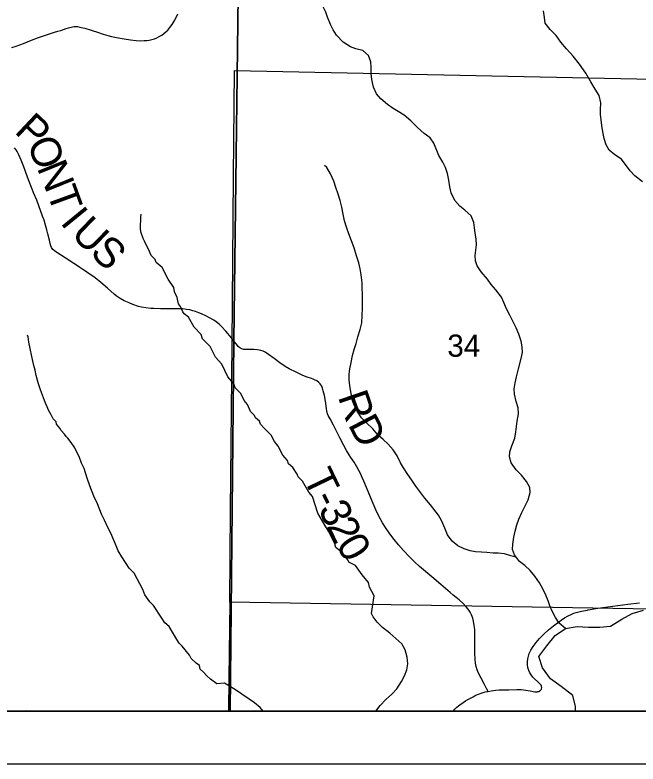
# Model space of a CAD drawing. Extents: x 0 to 34, y -8.9 to 22.
# Drawn here: x 27.768 to 28.944, y 14.5 to 15.913 of the extents above; entities that cross this region are included whole.
import ezdxf

# ---------------------------------------------------------------- set-up
doc = ezdxf.new("R2010")
doc.units = 0
for name, color, linetype in [('GM_X_Corporation', 7, 'Continuous'), ('GM_X_County_Road', 7, 'Continuous'), ('GM_X_Minor_River', 7, 'Continuous'), ('GM_X_Section_Text', 7, 'Continuous'), ('GM_X_Township_Road', 7, 'Continuous'), ('GM_X_Township_Road_Text', 7, 'Continuous'), ('SH_Data', 7, 'Continuous')]:
    doc.layers.add(name, color=color, linetype=linetype)

msp = doc.modelspace()

# ---------------------------------------------------------------- linework, layer by layer
at = {"layer": 'GM_X_Corporation'}
msp.add_lwpolyline([(23.7167, 19.34), (23.7167, 14.6), (30.5167, 14.6)], dxfattribs=at)
for points in [[(23.7167, 15.9913), (23.7167, 14.6), (28.1739, 14.6), (28.1809, 15.2987), (28.1918, 16.1509), (28.1846, 16.3341), (28.1817, 16.6637), (28.1928, 16.8054), (28.1882, 17.3108), (27.911, 17.3104), (27.4798, 17.3159), (27.0561, 17.3117), (26.7292, 17.3169), (26.394, 17.3229), (26.1361, 17.3278), (26.135, 17.3055), (26.1186, 15.9366), (25.7922, 15.939), (25.6785, 15.9418), (24.8268, 15.964), (24.2771, 15.9807), (24.0651, 15.9828)], [(28.1739, 14.6), (30.5167, 14.6), (30.5167, 16.7663), (30.4571, 16.7673), (29.5528, 16.7835), (28.3182, 16.8002), (28.1928, 16.8054), (28.1817, 16.6637), (28.1846, 16.3341), (28.1918, 16.1509), (28.1809, 15.2987)], [(29.0629, 15.7906), (29.0488, 14.7907), (28.1732, 14.8057), (28.1747, 14.9791), (28.1775, 15.2925), (28.1801, 15.6079), (28.182, 15.8086)], [(28.1707, 14.6), (29.0457, 14.6), (29.0488, 14.7907), (28.1732, 14.8057), (28.1713, 14.6617)]]:
    msp.add_lwpolyline(points, close=True, dxfattribs=at)
at = {"layer": 'GM_X_County_Road'}
for points in [[(28.6608, 14.6368), (28.6666, 14.638), (28.6753, 14.6391), (28.6819, 14.6397), (28.6877, 14.6397), (28.7001, 14.6402), (28.715, 14.6406), (28.7231, 14.6404), (28.7318, 14.6395), (28.7404, 14.638), (28.7489, 14.6365), (28.7513, 14.6362), (28.7531, 14.6362), (28.7548, 14.6366), (28.7568, 14.6371), (28.7585, 14.638), (28.7609, 14.6404), (28.7613, 14.6413), (28.762, 14.6439), (28.7617, 14.6466), (28.7609, 14.6486), (28.7592, 14.6509), (28.7549, 14.6551), (28.7482, 14.6609), (28.7451, 14.6641), (28.742, 14.668), (28.7396, 14.6718), (28.7374, 14.6763), (28.7359, 14.6819), (28.7351, 14.6869), (28.735, 14.6926), (28.7356, 14.6983), (28.7368, 14.7038), (28.7385, 14.7086), (28.7415, 14.7149), (28.7458, 14.7218), (28.7514, 14.7293), (28.7579, 14.7369), (28.7658, 14.7449), (28.775, 14.7533), (28.7841, 14.7608), (28.7986, 14.7714), (28.8047, 14.7757), (28.8118, 14.7798), (28.8186, 14.7829), (28.8227, 14.7845), (28.8273, 14.7858), (28.8321, 14.7871), (28.8373, 14.7883), (28.8487, 14.7906), (28.8495, 14.7907), (28.8679, 14.7939), (28.8869, 14.7966), (28.9246, 14.8014), (28.9467, 14.8042)], [(28.5946, 14.6), (28.5978, 14.6036), (28.6017, 14.6073), (28.605, 14.6099), (28.6074, 14.6117), (28.6135, 14.616), (28.6182, 14.6191), (28.6224, 14.6217), (28.6323, 14.627), (28.6362, 14.629), (28.6407, 14.631), (28.6445, 14.6324), (28.6479, 14.6336), (28.6515, 14.6347), (28.6553, 14.6359), (28.6608, 14.6368)]]:
    msp.add_lwpolyline(points, dxfattribs=at)
at = {"layer": 'GM_X_Minor_River'}
msp.add_line((27.7893, 14.6), (27.7892, 14.6012), dxfattribs=at)
for points in [[(28.3747, 15.8751), (28.3683, 15.8856), (28.3634, 15.8957), (28.3578, 15.9093), (28.3544, 15.919), (28.3485, 15.931), (28.3377, 15.9448), (28.3241, 15.9564), (28.3083, 15.9696), (28.2957, 15.9789), (28.2858, 15.987), (28.2737, 15.9966), (28.2592, 16.0068), (28.2482, 16.0145), (28.2346, 16.0257), (28.2258, 16.0356), (28.2255, 16.0466), (28.2283, 16.0568), (28.2249, 16.0668), (28.2139, 16.0764), (28.2041, 16.0784)], [(28.9523, 15.5987), (28.9379, 15.6096), (28.9292, 15.6191), (28.9123, 15.6411), (28.9001, 15.6492), (28.8894, 15.6585), (28.8837, 15.6682), (28.8801, 15.6802), (28.8776, 15.6928), (28.8754, 15.7047), (28.874, 15.7158), (28.8732, 15.7254), (28.8729, 15.7349), (28.8738, 15.7474), (28.8702, 15.7613), (28.8631, 15.7737), (28.8549, 15.7874), (28.8454, 15.8038), (28.8331, 15.8207), (28.8212, 15.8357), (28.8085, 15.8492), (28.798, 15.8622), (28.789, 15.8747), (28.7781, 15.8859), (28.7683, 15.8981), (28.7672, 15.9084), (28.7651, 15.9214)], [(28.8067, 14.7558), (28.7947, 14.7656), (28.788, 14.7765), (28.782, 14.7882), (28.7775, 14.7983), (28.7741, 14.8079), (28.77, 14.8188), (28.764, 14.8308), (28.7576, 14.8418), (28.749, 14.8543), (28.7404, 14.8653), (28.7301, 14.8749), (28.7198, 14.8822), (28.7104, 14.8948), (28.7071, 14.9048), (28.7075, 14.9147), (28.7096, 14.9283), (28.712, 14.9396), (28.7151, 14.9513), (28.7186, 14.9622), (28.7245, 14.9745), (28.7316, 14.9886), (28.7365, 14.9987), (28.7405, 15.0122), (28.7398, 15.0218), (28.7331, 15.0331), (28.7241, 15.0449), (28.7135, 15.0553), (28.7045, 15.0682), (28.7012, 15.0798), (28.7016, 15.0893), (28.7055, 15.1001), (28.711, 15.1147), (28.7131, 15.1265), (28.7143, 15.1371), (28.7158, 15.1469), (28.7179, 15.1605), (28.7173, 15.1723), (28.714, 15.1843), (28.7104, 15.1977), (28.71, 15.2077), (28.7117, 15.2194), (28.7141, 15.2307), (28.7173, 15.2431), (28.7235, 15.2649), (28.7255, 15.2762), (28.7249, 15.2873), (28.7234, 15.298), (28.7186, 15.3112), (28.7138, 15.3228), (28.7082, 15.3345), (28.7015, 15.3469), (28.6956, 15.359), (28.6907, 15.371), (28.6858, 15.3807), (28.6754, 15.3949), (28.6667, 15.4047), (28.6595, 15.4146), (28.6479, 15.4288), (28.64, 15.4398), (28.637, 15.4494), (28.6363, 15.4593), (28.6379, 15.4699), (28.6387, 15.4798), (28.638, 15.4905), (28.6362, 15.502), (28.6351, 15.5115), (28.6336, 15.5219), (28.6288, 15.5342), (28.6171, 15.545), (28.6075, 15.5527), (28.5981, 15.5633), (28.5911, 15.5777), (28.5885, 15.5892), (28.5868, 15.6015), (28.5843, 15.6142), (28.5806, 15.6257), (28.5753, 15.6359), (28.5678, 15.648), (28.5585, 15.6716), (28.5514, 15.6814), (28.5399, 15.6899), (28.5275, 15.7011), (28.5151, 15.7138), (28.5022, 15.7242), (28.4911, 15.7312), (28.4814, 15.7369), (28.4711, 15.7442), (28.4582, 15.7551), (28.4503, 15.7649), (28.4443, 15.7773), (28.4411, 15.7919), (28.4401, 15.803), (28.4398, 15.8148), (28.4395, 15.8251), (28.435, 15.8367), (28.4244, 15.8463), (28.4109, 15.8496), (28.4011, 15.8534), (28.3874, 15.8624), (28.3747, 15.8751)], [(28.7136, 14.8905), (28.7039, 14.8928), (28.6919, 14.8964), (28.6797, 14.8976), (28.6702, 14.898), (28.6585, 14.8989), (28.6482, 14.8998), (28.6368, 14.9003), (28.627, 14.9022), (28.6154, 14.9061), (28.6039, 14.9119), (28.5932, 14.9208), (28.5842, 14.9322), (28.579, 14.945), (28.5735, 14.9582), (28.5671, 14.9695), (28.552, 14.9892), (28.5411, 15.0018), (28.5317, 15.014), (28.5245, 15.0242), (28.517, 15.0356), (28.5095, 15.0466), (28.5009, 15.0587), (28.4956, 15.0685), (28.4893, 15.0817), (28.4814, 15.0931), (28.472, 15.1037), (28.4625, 15.1122), (28.4526, 15.121), (28.4432, 15.1324), (28.4315, 15.1436), (28.4216, 15.1535), (28.4138, 15.166), (28.4085, 15.1758), (28.4051, 15.1854), (28.4026, 15.1992), (28.3998, 15.2134), (28.3984, 15.2249), (28.3985, 15.2356), (28.3996, 15.2454), (28.4021, 15.2575), (28.4049, 15.2707), (28.4081, 15.2823), (28.4116, 15.2932), (28.4148, 15.306), (28.4192, 15.3199), (28.4224, 15.3327), (28.4235, 15.3601), (28.4235, 15.3764), (28.4233, 15.408), (28.4213, 15.4233), (28.4191, 15.4345), (28.4165, 15.4456), (28.4125, 15.4587), (28.4078, 15.4738), (28.4031, 15.4873), (28.3979, 15.5004), (28.3935, 15.5132), (28.3898, 15.5251), (28.387, 15.5378), (28.3845, 15.5509), (28.3816, 15.5635), (28.3779, 15.5755), (28.3735, 15.5879), (28.3694, 15.5995), (28.3635, 15.6134), (28.3561, 15.6259), (28.352, 15.6295)], [(28.4405, 14.7843), (28.4458, 14.8174), (28.4372, 14.8336), (28.4351, 14.8426), (28.4231, 14.8568), (28.4107, 14.8744), (28.3981, 14.8806), (28.3958, 14.8851), (28.3834, 14.9005), (28.3734, 14.9086), (28.3714, 14.9154), (28.3596, 14.9391), (28.3526, 14.9507), (28.3393, 14.9732), (28.3293, 15.0045), (28.3227, 15.0131), (28.3106, 15.0338), (28.3022, 15.0419), (28.3006, 15.0468), (28.292, 15.0592), (28.2839, 15.0666), (28.2823, 15.0727), (28.2731, 15.0828), (28.2648, 15.0997), (28.2575, 15.1083), (28.2512, 15.1203), (28.2381, 15.1337), (28.2312, 15.1415), (28.2295, 15.1472), (28.2215, 15.1535), (28.2199, 15.1576), (28.2126, 15.1651), (28.2067, 15.1782), (28.2001, 15.1857), (28.1938, 15.1989), (28.1834, 15.2097), (28.181, 15.2172), (28.1694, 15.2306), (28.158, 15.2547), (28.146, 15.2678), (28.1362, 15.2877), (28.122, 15.3022), (28.1192, 15.3105), (28.106, 15.3243), (28.0951, 15.3434), (28.0871, 15.3493), (28.0847, 15.3531), (28.0812, 15.3602), (28.08, 15.3636), (28.0765, 15.3685), (28.0736, 15.3806), (28.0689, 15.3907), (28.0673, 15.3994), (28.0568, 15.4148), (28.0454, 15.4369), (28.0343, 15.4466), (28.0326, 15.4519), (28.0246, 15.4597), (28.0198, 15.4713), (28.0171, 15.4758), (28.012, 15.4867), (28.0096, 15.4916), (28.0056, 15.5044), (28.0047, 15.5112), (28.0051, 15.5321), (28.0062, 15.5378)], [(28.1632, 14.6527), (28.1487, 14.6513), (28.1368, 14.6602), (28.1302, 14.6665), (28.1233, 14.6736), (28.1171, 14.6791), (28.1159, 14.6859), (28.1098, 14.6904), (28.1001, 14.6989), (28.097, 14.7057), (28.0831, 14.7225), (28.0777, 14.7281), (28.0734, 14.7348), (28.059, 14.7592), (28.0505, 14.7667), (28.0447, 14.7753), (28.0295, 14.7989), (28.0222, 14.8063), (28.0129, 14.8194), (28.0093, 14.8296), (27.9925, 14.86), (27.9836, 14.8693), (27.9696, 14.8907), (27.9626, 14.9023), (27.9578, 14.9151), (27.9539, 14.9234), (27.9487, 14.9355), (27.9437, 14.9452), (27.937, 14.9599), (27.9311, 14.9712), (27.9236, 14.9907), (27.9165, 15.0054), (27.9093, 15.025), (27.9038, 15.0393), (27.8982, 15.0574), (27.8934, 15.0675), (27.8887, 15.0804), (27.8844, 15.0886), (27.8808, 15.0965), (27.8738, 15.1066), (27.8676, 15.1149), (27.8645, 15.1182), (27.8611, 15.1227), (27.8549, 15.1294), (27.8522, 15.1335), (27.8464, 15.1414), (27.8455, 15.1459), (27.8397, 15.1515), (27.8362, 15.1586), (27.8335, 15.1635), (27.8311, 15.168), (27.8284, 15.1741), (27.826, 15.1797), (27.8232, 15.1857), (27.8197, 15.1959), (27.8161, 15.2061), (27.8121, 15.2174), (27.808, 15.2332), (27.8056, 15.243), (27.8032, 15.2521), (27.7998, 15.2687), (27.7966, 15.2838), (27.7937, 15.2959), (27.7924, 15.3061), (27.7916, 15.3095)], [(28.449, 14.6), (28.4571, 14.6107), (28.4678, 14.6217), (28.4793, 14.6319), (28.4885, 14.6417), (28.4974, 14.6554), (28.5028, 14.6662), (28.5071, 14.6775), (28.5091, 14.6888), (28.5081, 14.7014), (28.5042, 14.7157), (28.4982, 14.727), (28.4868, 14.737), (28.4751, 14.7466), (28.4614, 14.7575), (28.4516, 14.7678), (28.4437, 14.778), (28.4405, 14.7843)], [(28.8258, 14.6), (28.826, 14.6084), (28.8207, 14.6293), (28.7984, 14.6464), (28.7787, 14.6605), (28.7636, 14.6817), (28.7568, 14.703), (28.7719, 14.7231), (28.7871, 14.7425), (28.8067, 14.7558), (28.8287, 14.7596), (28.8506, 14.7584), (28.8718, 14.7584), (28.8918, 14.7603), (28.9134, 14.7733), (28.9327, 14.7839), (28.9542, 14.7903)], [(28.2364, 14.6), (28.2305, 14.6064), (28.2199, 14.6153), (28.2095, 14.6222), (28.1958, 14.6315), (28.1858, 14.6388), (28.1729, 14.647), (28.1632, 14.6527)]]:
    msp.add_lwpolyline(points, dxfattribs=at)
at = {"layer": 'GM_X_Township_Road'}
for points in [[(27.7621, 15.8519), (27.7703, 15.8547), (27.7836, 15.8598), (27.7992, 15.8661), (27.812, 15.8709), (27.8232, 15.8747), (27.8308, 15.8771), (27.8368, 15.8791), (27.8423, 15.8808), (27.8489, 15.8829), (27.8541, 15.8844), (27.8592, 15.886), (27.8644, 15.8878), (27.8689, 15.889), (27.8736, 15.8902), (27.8765, 15.8908), (27.8796, 15.8914), (27.8826, 15.8916), (27.8857, 15.8914), (27.89, 15.8907), (27.896, 15.8892), (27.8994, 15.8884), (27.9032, 15.8872), (27.9079, 15.8858), (27.9133, 15.8841), (27.9233, 15.8809), (27.9345, 15.8772), (27.9428, 15.8746), (27.95, 15.8727), (27.9597, 15.8706), (27.9738, 15.8682), (27.9861, 15.8665), (27.9966, 15.8654), (28.0046, 15.8649), (28.0114, 15.865), (28.0164, 15.8653), (28.0213, 15.866), (28.0262, 15.8671), (28.0309, 15.8685), (28.0356, 15.8703), (28.04, 15.8725), (28.0448, 15.8753), (28.0489, 15.8783), (28.0526, 15.8815), (28.0561, 15.885), (28.0602, 15.8897), (28.0642, 15.8953), (28.0682, 15.9015), (28.0721, 15.9086), (28.0754, 15.9158)], [(28.1817, 15.2973), (28.1811, 15.2981), (28.1765, 15.3041), (28.1657, 15.3169), (28.1578, 15.3255), (28.1533, 15.3298), (28.1474, 15.3343), (28.1428, 15.3375), (28.1348, 15.3422), (28.1277, 15.3459), (28.1199, 15.3493), (28.1145, 15.3514), (28.1084, 15.3537), (28.1035, 15.3552), (28.0976, 15.3568), (28.0914, 15.3579), (28.0847, 15.3587), (28.0772, 15.3591), (28.0618, 15.3592), (28.0513, 15.3589), (28.0427, 15.3589), (28.0299, 15.3594), (28.0239, 15.3598), (28.015, 15.3606), (28.0065, 15.3621), (28.0011, 15.3635), (27.9905, 15.3671), (27.9831, 15.37), (27.9741, 15.3742), (27.9664, 15.3782), (27.9623, 15.381), (27.9588, 15.3834), (27.9549, 15.3867), (27.9424, 15.3978), (27.9298, 15.4089), (27.9191, 15.4174), (27.9131, 15.4218), (27.9059, 15.4265), (27.901, 15.4298), (27.8959, 15.4333), (27.8901, 15.437), (27.8839, 15.4413), (27.8788, 15.4445), (27.8622, 15.455), (27.8467, 15.4649), (27.8423, 15.4684), (27.8395, 15.4709), (27.837, 15.4744), (27.8356, 15.4778), (27.8342, 15.4819), (27.8328, 15.4886), (27.8299, 15.5002), (27.8281, 15.5082), (27.8254, 15.517), (27.8227, 15.5263), (27.82, 15.5336), (27.813, 15.5535), (27.809, 15.564), (27.8036, 15.5764), (27.7989, 15.5877), (27.7944, 15.599), (27.7915, 15.6071), (27.7876, 15.6183), (27.7846, 15.6271), (27.7796, 15.6397), (27.7752, 15.6492), (27.7719, 15.6559), (27.7698, 15.659), (27.7668, 15.6629)], [(28.6608, 14.6368), (28.658, 14.6425), (28.6541, 14.6503), (28.6475, 14.6622), (28.6427, 14.6716), (28.6401, 14.6778), (28.6382, 14.6837), (28.6368, 14.6904), (28.6361, 14.6978), (28.6357, 14.7089), (28.636, 14.743), (28.6356, 14.7541), (28.6347, 14.7615), (28.6333, 14.7694), (28.6317, 14.7754), (28.6295, 14.7812), (28.6267, 14.7868), (28.6234, 14.792), (28.6195, 14.7969), (28.6135, 14.8032), (28.6061, 14.8098), (28.5951, 14.8188), (28.5893, 14.8236), (28.5714, 14.8389), (28.5544, 14.8535), (28.5311, 14.873), (28.5219, 14.8814), (28.5118, 14.8914), (28.5009, 14.9031), (28.4915, 14.9138), (28.4837, 14.9234), (28.4755, 14.9343), (28.4673, 14.946), (28.4613, 14.9554), (28.4544, 14.9679), (28.4486, 14.9796), (28.4437, 14.9917), (28.426, 15.034), (28.4233, 15.0406), (28.4203, 15.0472), (28.4169, 15.0538), (28.4129, 15.0608), (28.4077, 15.0693), (28.402, 15.0782), (28.3986, 15.0834), (28.3934, 15.0918), (28.3882, 15.101), (28.3807, 15.1153), (28.3691, 15.1393), (28.3624, 15.1511), (28.3605, 15.1546), (28.3591, 15.1574), (28.3579, 15.161), (28.3567, 15.1663), (28.3558, 15.1699), (28.3549, 15.176), (28.3537, 15.1847), (28.3519, 15.1951), (28.3497, 15.2041), (28.3483, 15.209), (28.3468, 15.2128), (28.3453, 15.2155), (28.3438, 15.2176), (28.3411, 15.2202), (28.3376, 15.2228), (28.3332, 15.2251), (28.3308, 15.226), (28.3274, 15.2273), (28.3194, 15.2302), (28.3114, 15.2334), (28.2984, 15.2393), (28.2851, 15.2459), (28.2776, 15.2502), (28.2678, 15.2568), (28.2568, 15.2649), (28.2464, 15.2728), (28.2403, 15.277), (28.2364, 15.2789), (28.2317, 15.2804), (28.2257, 15.2816), (28.2189, 15.2822), (28.2115, 15.2822), (28.2034, 15.2819), (28.1992, 15.2824), (28.1957, 15.2835), (28.1925, 15.2853), (28.1892, 15.2881), (28.1856, 15.2923), (28.1817, 15.2973)]]:
    msp.add_lwpolyline(points, dxfattribs=at)
at = {"layer": 'SH_Data'}
for points in [[(23.6167, 21.5), (30.6167, 21.5), (30.6167, 14.5), (23.6167, 14.5)], [(23.7167, 21.4), (30.5167, 21.4), (30.5167, 14.6), (23.7167, 14.6)]]:
    msp.add_lwpolyline(points, close=True, dxfattribs=at)

# ---------------------------------------------------------------- texts
at = {"layer": 'GM_X_Section_Text'}
msp.add_text('34', height=0.04186, rotation=0, dxfattribs=at).set_placement((28.5838, 15.2685))
at = {"layer": 'GM_X_Township_Road_Text'}
for s, rotation, p in [('P', 316.7978, (27.7649, 15.6921)), ('O', 292.7992, (27.7893, 15.671)), ('N', 292.0429, (27.8086, 15.6251)), ('T', 289.9882, (27.8272, 15.5792)), ('I', 309.2078, (27.8519, 15.5213)), ('U', 315.5616, (27.8713, 15.4981)), ('S', 315.9637, (27.9073, 15.4628)), ('R', 288.8916, (28.3768, 15.1933)), ('D', 297.561, (28.3955, 15.1407)), ('T', 295.6163, (28.3108, 15.0407)), ('-', 295.6514, (28.3292, 15.0024)), ('3', 295.766, (28.3394, 14.9812)), ('2', 296.2976, (28.3548, 14.9492)), ('0', 300.5873, (28.3726, 14.9137))]:
    msp.add_text(s, height=0.0568, rotation=rotation, dxfattribs=at).set_placement(p)

doc.saveas('drawing.dxf')
